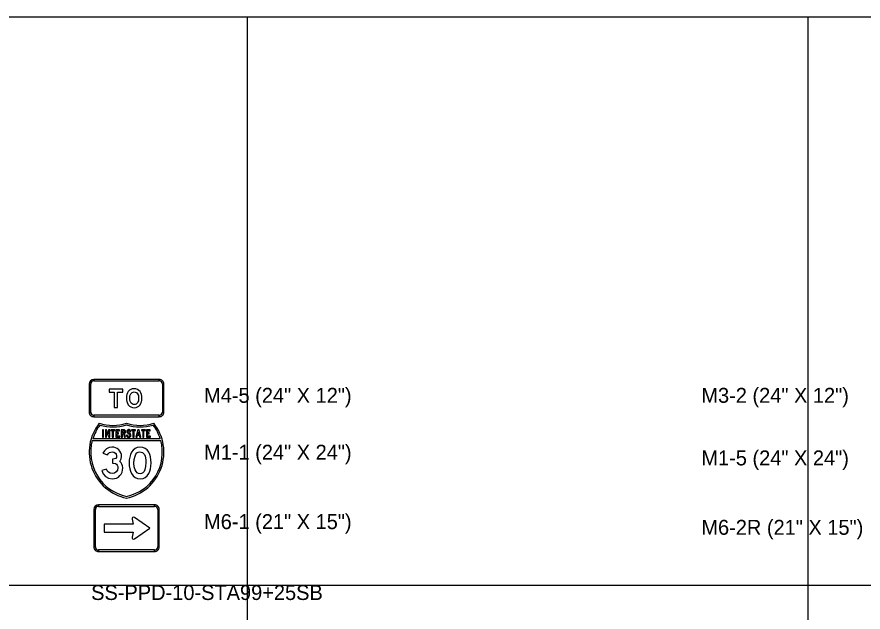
# Model space of a CAD drawing. Extents: x 1001568 to 1002149, y 1840825 to 1841423.
# Drawn here: x 1001914.49 to 1001937.13, y 1841294.75 to 1841310.67 of the extents above; entities that cross this region are included whole.
import ezdxf

# ---------------------------------------------------------------- set-up
doc = ezdxf.new("R2010")
doc.units = 0
for name, color, linetype in [('40', 7, 'Continuous'), ('R_No Plot', 7, 'Continuous'), ('SIGNS', 7, 'Continuous')]:
    doc.layers.add(name, color=color, linetype=linetype)

msp = doc.modelspace()

# ---------------------------------------------------------------- linework, layer by layer
at = {"layer": 'R_No Plot'}
for p, q in [((1001920.65, 1841310.667), (1001920.65, 1841248.127)), ((1001935.65, 1841310.667), (1001935.65, 1841248.127)), ((1001890.65, 1841295.469), (1001982.133, 1841295.469))]:
    msp.add_line(p, q, dxfattribs=at)
msp.add_lwpolyline([(1001886.411, 1841310.667), (1001964.232, 1841310.667), (1001964.232, 1841307.694), (1001968.454, 1841307.694), (1001968.454, 1841306.882), (1001982.133, 1841306.882), (1001982.133, 1841248.127), (1001886.411, 1841248.127)], close=True, dxfattribs=at)
at = {"layer": 'SIGNS'}
for p, q in [((1001916.42, 1841300.846), (1001916.42, 1841300.096)), ((1001916.42, 1841300.846), (1001916.462, 1841300.846)), ((1001918.295, 1841300.971), (1001916.545, 1841300.971)), ((1001916.545, 1841300.93), (1001916.545, 1841300.971)), ((1001918.295, 1841300.971), (1001918.295, 1841300.93)), ((1001918.379, 1841300.846), (1001918.42, 1841300.846)), ((1001918.42, 1841300.096), (1001918.42, 1841300.846)), ((1001916.462, 1841300.096), (1001916.42, 1841300.096)), ((1001916.545, 1841299.971), (1001916.545, 1841300.013)), ((1001916.545, 1841299.971), (1001918.295, 1841299.971)), ((1001918.295, 1841300.013), (1001918.295, 1841299.971)), ((1001918.42, 1841300.096), (1001918.379, 1841300.096)), ((1001916.808, 1841299.625), (1001916.78, 1841299.625)), ((1001916.78, 1841299.625), (1001916.78, 1841299.421)), ((1001916.808, 1841299.421), (1001916.808, 1841299.625)), ((1001916.883, 1841299.625), (1001916.855, 1841299.625)), ((1001916.855, 1841299.625), (1001916.855, 1841299.421)), ((1001916.939, 1841299.503), (1001916.883, 1841299.625)), ((1001916.883, 1841299.421), (1001916.883, 1841299.559)), ((1001916.883, 1841299.559), (1001916.947, 1841299.421)), ((1001916.97, 1841299.625), (1001916.939, 1841299.625)), ((1001916.939, 1841299.625), (1001916.939, 1841299.503)), ((1001916.97, 1841299.421), (1001916.97, 1841299.625)), ((1001917.105, 1841299.625), (1001917, 1841299.625)), ((1001917, 1841299.625), (1001917, 1841299.599)), ((1001917, 1841299.599), (1001917.038, 1841299.599)), ((1001917.038, 1841299.599), (1001917.038, 1841299.421)), ((1001917.067, 1841299.421), (1001917.067, 1841299.599)), ((1001917.067, 1841299.599), (1001917.105, 1841299.599)), ((1001917.105, 1841299.599), (1001917.105, 1841299.625)), ((1001917.233, 1841299.625), (1001917.136, 1841299.625)), ((1001917.136, 1841299.625), (1001917.136, 1841299.421)), ((1001917.166, 1841299.545), (1001917.166, 1841299.597)), ((1001917.166, 1841299.597), (1001917.233, 1841299.597)), ((1001917.208, 1841299.545), (1001917.166, 1841299.545)), ((1001917.166, 1841299.449), (1001917.166, 1841299.517)), ((1001917.166, 1841299.517), (1001917.208, 1841299.517)), ((1001917.241, 1841299.449), (1001917.166, 1841299.449)), ((1001917.208, 1841299.517), (1001917.208, 1841299.545)), ((1001917.233, 1841299.597), (1001917.233, 1841299.625)), ((1001917.241, 1841299.421), (1001917.241, 1841299.449)), ((1001917.447, 1841299.482), (1001917.419, 1841299.482)), ((1001917.419, 1841299.482), (1001917.419, 1841299.48)), ((1001917.419, 1841299.48), (1001917.42, 1841299.468)), ((1001917.42, 1841299.468), (1001917.423, 1841299.456)), ((1001917.423, 1841299.456), (1001917.428, 1841299.446)), ((1001917.432, 1841299.596), (1001917.428, 1841299.576)), ((1001917.428, 1841299.576), (1001917.429, 1841299.566)), ((1001917.428, 1841299.446), (1001917.435, 1841299.436)), ((1001917.429, 1841299.566), (1001917.432, 1841299.557)), ((1001917.444, 1841299.613), (1001917.432, 1841299.596)), ((1001917.432, 1841299.557), (1001917.437, 1841299.548)), ((1001917.435, 1841299.436), (1001917.444, 1841299.428)), ((1001917.437, 1841299.548), (1001917.444, 1841299.54)), ((1001917.452, 1841299.62), (1001917.444, 1841299.613)), ((1001917.444, 1841299.54), (1001917.477, 1841299.516)), ((1001917.449, 1841299.469), (1001917.447, 1841299.482)), ((1001917.455, 1841299.458), (1001917.449, 1841299.469)), ((1001917.461, 1841299.625), (1001917.452, 1841299.62)), ((1001917.464, 1841299.449), (1001917.455, 1841299.458)), ((1001917.457, 1841299.577), (1001917.459, 1841299.586)), ((1001917.458, 1841299.57), (1001917.457, 1841299.577)), ((1001917.461, 1841299.564), (1001917.458, 1841299.57)), ((1001917.459, 1841299.586), (1001917.464, 1841299.594)), ((1001917.47, 1841299.628), (1001917.461, 1841299.625)), ((1001917.477, 1841299.553), (1001917.461, 1841299.564)), ((1001917.464, 1841299.594), (1001917.472, 1841299.599)), ((1001917.477, 1841299.446), (1001917.464, 1841299.449)), ((1001917.481, 1841299.629), (1001917.47, 1841299.628)), ((1001917.472, 1841299.599), (1001917.482, 1841299.601)), ((1001917.501, 1841299.536), (1001917.477, 1841299.553)), ((1001917.477, 1841299.516), (1001917.49, 1841299.507)), ((1001917.489, 1841299.449), (1001917.477, 1841299.446)), ((1001917.492, 1841299.628), (1001917.481, 1841299.629)), ((1001917.482, 1841299.601), (1001917.492, 1841299.599)), ((1001917.498, 1841299.456), (1001917.489, 1841299.449)), ((1001917.49, 1841299.507), (1001917.497, 1841299.5)), ((1001917.502, 1841299.625), (1001917.492, 1841299.628)), ((1001917.492, 1841299.599), (1001917.499, 1841299.594)), ((1001917.497, 1841299.5), (1001917.504, 1841299.49)), ((1001917.504, 1841299.467), (1001917.498, 1841299.456)), ((1001917.499, 1841299.594), (1001917.503, 1841299.587)), ((1001917.516, 1841299.523), (1001917.501, 1841299.536)), ((1001917.511, 1841299.621), (1001917.502, 1841299.625)), ((1001917.503, 1841299.587), (1001917.506, 1841299.577)), ((1001917.504, 1841299.49), (1001917.506, 1841299.479)), ((1001917.506, 1841299.479), (1001917.504, 1841299.467)), ((1001917.506, 1841299.577), (1001917.534, 1841299.577)), ((1001917.51, 1841299.427), (1001917.519, 1841299.436)), ((1001917.519, 1841299.614), (1001917.511, 1841299.621)), ((1001917.524, 1841299.513), (1001917.516, 1841299.523)), ((1001917.53, 1841299.598), (1001917.519, 1841299.614)), ((1001917.519, 1841299.436), (1001917.526, 1841299.445)), ((1001917.53, 1841299.502), (1001917.524, 1841299.513)), ((1001917.526, 1841299.445), (1001917.531, 1841299.455)), ((1001917.534, 1841299.577), (1001917.53, 1841299.598)), ((1001917.533, 1841299.491), (1001917.53, 1841299.502)), ((1001917.531, 1841299.455), (1001917.533, 1841299.467)), ((1001917.534, 1841299.479), (1001917.533, 1841299.491)), ((1001917.533, 1841299.467), (1001917.534, 1841299.479)), ((1001917.66, 1841299.625), (1001917.555, 1841299.625)), ((1001917.555, 1841299.625), (1001917.555, 1841299.599)), ((1001917.555, 1841299.599), (1001917.592, 1841299.599)), ((1001917.592, 1841299.599), (1001917.592, 1841299.421)), ((1001917.622, 1841299.421), (1001917.622, 1841299.599)), ((1001917.622, 1841299.599), (1001917.66, 1841299.599)), ((1001917.66, 1841299.599), (1001917.66, 1841299.625)), ((1001917.924, 1841299.625), (1001917.819, 1841299.625)), ((1001917.819, 1841299.625), (1001917.819, 1841299.599)), ((1001917.819, 1841299.599), (1001917.856, 1841299.599)), ((1001917.856, 1841299.599), (1001917.856, 1841299.421)), ((1001917.886, 1841299.421), (1001917.886, 1841299.599)), ((1001917.886, 1841299.599), (1001917.924, 1841299.599)), ((1001917.924, 1841299.599), (1001917.924, 1841299.625)), ((1001918.052, 1841299.625), (1001917.955, 1841299.625)), ((1001917.955, 1841299.625), (1001917.955, 1841299.421)), ((1001917.984, 1841299.545), (1001917.984, 1841299.597)), ((1001917.984, 1841299.597), (1001918.052, 1841299.597)), ((1001918.027, 1841299.545), (1001917.984, 1841299.545)), ((1001917.984, 1841299.449), (1001917.984, 1841299.517)), ((1001917.984, 1841299.517), (1001918.027, 1841299.517)), ((1001918.06, 1841299.449), (1001917.984, 1841299.449)), ((1001918.027, 1841299.517), (1001918.027, 1841299.545)), ((1001918.052, 1841299.597), (1001918.052, 1841299.625)), ((1001918.06, 1841299.421), (1001918.06, 1841299.449)), ((1001918.324, 1841299.379), (1001916.516, 1841299.379)), ((1001916.78, 1841299.421), (1001916.808, 1841299.421)), ((1001916.855, 1841299.421), (1001916.883, 1841299.421)), ((1001916.947, 1841299.421), (1001916.97, 1841299.421)), ((1001917.038, 1841299.421), (1001917.067, 1841299.421)), ((1001917.136, 1841299.421), (1001917.241, 1841299.421)), ((1001917.444, 1841299.428), (1001917.454, 1841299.422)), ((1001917.454, 1841299.422), (1001917.465, 1841299.418)), ((1001917.465, 1841299.418), (1001917.477, 1841299.417)), ((1001917.477, 1841299.417), (1001917.489, 1841299.418)), ((1001917.489, 1841299.418), (1001917.5, 1841299.421)), ((1001917.5, 1841299.421), (1001917.51, 1841299.427)), ((1001917.592, 1841299.421), (1001917.622, 1841299.421)), ((1001917.856, 1841299.421), (1001917.886, 1841299.421)), ((1001917.955, 1841299.421), (1001918.06, 1841299.421)), ((1001916.545, 1841297.491), (1001916.587, 1841297.491)), ((1001916.67, 1841297.574), (1001916.67, 1841297.616)), ((1001918.17, 1841297.616), (1001918.17, 1841297.574)), ((1001918.254, 1841297.491), (1001918.295, 1841297.491)), ((1001917.567, 1841297.232), (1001917.597, 1841297.1)), ((1001918.045, 1841296.991), (1001917.63, 1841297.276)), ((1001917.597, 1841297.1), (1001916.826, 1841297.1)), ((1001916.826, 1841297.1), (1001916.826, 1841296.882)), ((1001917.63, 1841296.706), (1001918.045, 1841296.991)), ((1001916.826, 1841296.882), (1001917.597, 1841296.882)), ((1001917.597, 1841296.882), (1001917.567, 1841296.75)), ((1001916.587, 1841296.491), (1001916.545, 1841296.491)), ((1001916.67, 1841296.366), (1001916.67, 1841296.408)), ((1001918.17, 1841296.408), (1001918.17, 1841296.366)), ((1001918.295, 1841296.491), (1001918.254, 1841296.491))]:
    msp.add_line(p, q, dxfattribs=at)
for points in [[(1001916.42, 1841300.846), (1001916.42, 1841300.096), (1001916.462, 1841300.096), (1001916.462, 1841300.846), (1001916.42, 1841300.846), (1001916.42, 1841300.846)], [(1001918.295, 1841300.971), (1001916.545, 1841300.971), (1001916.545, 1841300.93), (1001918.295, 1841300.93), (1001918.295, 1841300.971), (1001918.295, 1841300.971)], [(1001918.42, 1841300.096), (1001918.42, 1841300.846), (1001918.379, 1841300.846), (1001918.379, 1841300.096), (1001918.42, 1841300.096), (1001918.42, 1841300.096)], [(1001917.093, 1841300.221), (1001917.179, 1841300.221), (1001917.179, 1841300.629), (1001917.322, 1841300.629), (1001917.322, 1841300.712), (1001916.951, 1841300.712), (1001916.951, 1841300.629), (1001917.093, 1841300.629)], [(1001916.545, 1841299.971), (1001918.295, 1841299.971), (1001918.295, 1841300.013), (1001916.545, 1841300.013), (1001916.545, 1841299.971), (1001916.545, 1841299.971)], [(1001916.758, 1841298.532), (1001916.795, 1841298.441), (1001916.859, 1841298.371), (1001916.942, 1841298.326), (1001917.04, 1841298.311), (1001917.1, 1841298.316), (1001917.155, 1841298.332), (1001917.202, 1841298.358), (1001917.244, 1841298.396), (1001917.276, 1841298.439), (1001917.299, 1841298.489), (1001917.313, 1841298.544), (1001917.318, 1841298.605), (1001917.313, 1841298.654), (1001917.298, 1841298.699), (1001917.274, 1841298.739), (1001917.24, 1841298.775), (1001917.274, 1841298.844), (1001917.286, 1841298.91), (1001917.281, 1841298.961), (1001917.267, 1841299.008), (1001917.244, 1841299.05), (1001917.211, 1841299.088), (1001917.171, 1841299.12), (1001917.128, 1841299.142), (1001917.08, 1841299.156), (1001917.029, 1841299.16), (1001916.953, 1841299.149), (1001916.884, 1841299.114), (1001916.827, 1841299.062), (1001916.79, 1841298.997), (1001916.912, 1841298.952), (1001916.934, 1841298.987), (1001916.962, 1841299.012), (1001916.996, 1841299.027), (1001917.036, 1841299.032), (1001917.082, 1841299.024), (1001917.121, 1841299.001), (1001917.147, 1841298.966), (1001917.156, 1841298.922), (1001917.15, 1841298.884), (1001917.132, 1841298.858), (1001917.101, 1841298.843), (1001917.059, 1841298.84), (1001917.043, 1841298.84), (1001917.043, 1841298.728), (1001917.05, 1841298.728), (1001917.121, 1841298.722), (1001917.15, 1841298.704), (1001917.171, 1841298.678), (1001917.183, 1841298.644), (1001917.187, 1841298.603), (1001917.177, 1841298.543), (1001917.145, 1841298.496), (1001917.098, 1841298.465), (1001917.04, 1841298.455), (1001916.985, 1841298.463), (1001916.939, 1841298.487), (1001916.904, 1841298.523), (1001916.885, 1841298.57)], [(1001916.545, 1841297.491), (1001916.545, 1841296.491), (1001916.587, 1841296.491), (1001916.587, 1841297.491), (1001916.545, 1841297.491), (1001916.545, 1841297.491)], [(1001918.17, 1841297.616), (1001916.67, 1841297.616), (1001916.67, 1841297.574), (1001918.17, 1841297.574), (1001918.17, 1841297.616), (1001918.17, 1841297.616)], [(1001918.295, 1841296.491), (1001918.295, 1841297.491), (1001918.254, 1841297.491), (1001918.254, 1841296.491), (1001918.295, 1841296.491), (1001918.295, 1841296.491)], [(1001916.67, 1841296.366), (1001918.17, 1841296.366), (1001918.17, 1841296.408), (1001916.67, 1841296.408), (1001916.67, 1841296.366), (1001916.67, 1841296.366)]]:
    msp.add_lwpolyline(points, close=True, dxfattribs=at)
for points in [[(1001917.832, 1841300.47), (1001917.829, 1841300.52), (1001917.819, 1841300.566), (1001917.803, 1841300.607), (1001917.781, 1841300.643), (1001917.75, 1841300.677), (1001917.713, 1841300.702), (1001917.67, 1841300.716), (1001917.622, 1841300.721), (1001917.574, 1841300.716), (1001917.532, 1841300.702), (1001917.496, 1841300.678), (1001917.465, 1841300.644), (1001917.444, 1841300.608), (1001917.429, 1841300.567), (1001917.42, 1841300.522), (1001917.417, 1841300.473), (1001917.42, 1841300.422), (1001917.429, 1841300.375), (1001917.444, 1841300.333), (1001917.466, 1841300.294), (1001917.497, 1841300.258), (1001917.534, 1841300.232), (1001917.577, 1841300.217), (1001917.626, 1841300.212), (1001917.674, 1841300.217), (1001917.717, 1841300.232), (1001917.753, 1841300.258), (1001917.784, 1841300.293), (1001917.805, 1841300.331), (1001917.82, 1841300.373), (1001917.829, 1841300.419), (1001917.832, 1841300.47)], [(1001917.743, 1841300.477), (1001917.741, 1841300.435), (1001917.736, 1841300.399), (1001917.726, 1841300.369), (1001917.714, 1841300.344), (1001917.697, 1841300.325), (1001917.677, 1841300.311), (1001917.653, 1841300.303), (1001917.626, 1841300.3), (1001917.596, 1841300.303), (1001917.57, 1841300.314), (1001917.548, 1841300.331), (1001917.531, 1841300.356), (1001917.512, 1841300.407), (1001917.506, 1841300.471), (1001917.512, 1841300.532), (1001917.531, 1841300.582), (1001917.549, 1841300.606), (1001917.571, 1841300.623), (1001917.596, 1841300.633), (1001917.626, 1841300.637), (1001917.654, 1841300.633), (1001917.679, 1841300.624), (1001917.7, 1841300.607), (1001917.717, 1841300.584), (1001917.737, 1841300.536), (1001917.743, 1841300.477)], [(1001916.69, 1841299.796), (1001916.69, 1841299.796)], [(1001916.705, 1841299.748), (1001916.705, 1841299.748)], [(1001917.42, 1841299.754), (1001917.42, 1841299.754)], [(1001918.135, 1841299.748), (1001918.135, 1841299.748)], [(1001918.151, 1841299.796), (1001918.151, 1841299.796)], [(1001917.31, 1841299.421), (1001917.31, 1841299.518), (1001917.337, 1841299.518), (1001917.364, 1841299.421), (1001917.393, 1841299.421), (1001917.363, 1841299.521), (1001917.376, 1841299.529), (1001917.385, 1841299.54), (1001917.391, 1841299.553), (1001917.393, 1841299.568), (1001917.392, 1841299.58), (1001917.389, 1841299.591), (1001917.385, 1841299.601), (1001917.379, 1841299.609), (1001917.371, 1841299.616), (1001917.362, 1841299.621), (1001917.351, 1841299.624), (1001917.339, 1841299.625), (1001917.277, 1841299.625), (1001917.277, 1841299.421), (1001917.31, 1841299.421)], [(1001917.31, 1841299.545), (1001917.31, 1841299.597), (1001917.339, 1841299.597), (1001917.35, 1841299.595), (1001917.358, 1841299.59), (1001917.364, 1841299.582), (1001917.366, 1841299.571), (1001917.364, 1841299.559), (1001917.359, 1841299.551), (1001917.351, 1841299.547), (1001917.34, 1841299.545), (1001917.31, 1841299.545)], [(1001917.703, 1841299.421), (1001917.717, 1841299.477), (1001917.761, 1841299.477), (1001917.775, 1841299.421), (1001917.805, 1841299.421), (1001917.754, 1841299.625), (1001917.725, 1841299.625), (1001917.673, 1841299.421), (1001917.703, 1841299.421)], [(1001917.724, 1841299.506), (1001917.738, 1841299.565), (1001917.754, 1841299.506), (1001917.724, 1841299.506)], [(1001916.504, 1841299.337), (1001917.047, 1841299.337), (1001917.574, 1841299.337), (1001918.336, 1841299.337)], [(1001917.78, 1841299.16), (1001917.709, 1841299.151), (1001917.647, 1841299.125), (1001917.595, 1841299.081), (1001917.552, 1841299.02), (1001917.525, 1841298.96), (1001917.506, 1841298.894), (1001917.495, 1841298.82), (1001917.491, 1841298.739), (1001917.495, 1841298.655), (1001917.506, 1841298.579), (1001917.525, 1841298.511), (1001917.552, 1841298.451), (1001917.595, 1841298.39), (1001917.649, 1841298.346), (1001917.713, 1841298.32), (1001917.788, 1841298.311), (1001917.861, 1841298.32), (1001917.923, 1841298.346), (1001917.976, 1841298.391), (1001918.019, 1841298.453), (1001918.044, 1841298.511), (1001918.062, 1841298.578), (1001918.072, 1841298.652), (1001918.076, 1841298.734), (1001918.072, 1841298.819), (1001918.061, 1841298.896), (1001918.043, 1841298.963), (1001918.018, 1841299.022), (1001917.975, 1841299.082), (1001917.921, 1841299.125), (1001917.856, 1841299.151), (1001917.78, 1841299.16)], [(1001917.94, 1841298.743), (1001917.932, 1841298.642), (1001917.911, 1841298.557), (1001917.888, 1841298.509), (1001917.859, 1841298.475), (1001917.824, 1841298.454), (1001917.783, 1841298.447), (1001917.74, 1841298.454), (1001917.704, 1841298.473), (1001917.674, 1841298.505), (1001917.65, 1841298.55), (1001917.627, 1841298.632), (1001917.619, 1841298.732), (1001917.626, 1841298.83), (1001917.648, 1841298.917), (1001917.671, 1841298.967), (1001917.699, 1841299.002), (1001917.733, 1841299.024), (1001917.773, 1841299.031), (1001917.812, 1841299.026), (1001917.846, 1841299.013), (1001917.874, 1841298.99), (1001917.898, 1841298.959), (1001917.916, 1841298.918), (1001917.929, 1841298.869), (1001917.937, 1841298.81), (1001917.94, 1841298.743)], [(1001917.42, 1841297.837), (1001917.42, 1841297.837)], [(1001917.42, 1841297.796), (1001917.42, 1841297.796)]]:
    msp.add_lwpolyline(points, dxfattribs=at)
for centre, radius, start, end in [((1001916.545, 1841300.846), 0.125, 90.0002, 179.9998), ((1001916.545, 1841300.846), 0.125, 90.0002, 179.9998), ((1001916.545, 1841300.846), 0.0833, 90.0002, 179.9998), ((1001918.295, 1841300.846), 0.125, 360, 90.0002), ((1001918.295, 1841300.846), 0.125, 360, 90.0002), ((1001918.295, 1841300.846), 0.0833, 360, 90.0002), ((1001916.545, 1841300.096), 0.125, 179.9998, 270.0001), ((1001916.545, 1841300.096), 0.125, 179.9998, 270.0001), ((1001916.545, 1841300.096), 0.0833, 179.9998, 270.0001), ((1001918.295, 1841300.096), 0.125, 270.0001, 0.0003), ((1001918.295, 1841300.096), 0.125, 270.0001, 0.0003), ((1001918.295, 1841300.096), 0.0833, 270.0001, 0.0003), ((1001917.67, 1841299.021), 1.25, 141.669, 258.463), ((1001917.67, 1841299.02), 1.208, 142.9959, 162.6952), ((1001917.055, 1841300.991), 1.25, 253.009, 286.9909), ((1001917.052, 1841300.992), 1.292, 254.4391, 286.5746), ((1001917.17, 1841299.021), 1.25, 281.5371, 38.3311), ((1001917.785, 1841300.991), 1.25, 253.0091, 286.9911), ((1001917.789, 1841300.992), 1.292, 253.4255, 285.561), ((1001917.17, 1841299.02), 1.208, 17.3047, 37.0041), ((1001917.67, 1841299.02), 1.208, 164.7534, 258.0704), ((1001917.17, 1841299.02), 1.208, 281.9296, 15.2467), ((1001917.17, 1841299.02), 1.208, 281.9296126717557, 281.9296393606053), ((1001917.67, 1841299.02), 1.208, 258.0704, 258.0705), ((1001916.67, 1841297.491), 0.125, 90.0002, 179.9998), ((1001916.67, 1841297.491), 0.0833, 90.0002, 179.9998), ((1001918.17, 1841297.491), 0.125, 0, 90.0002), ((1001918.17, 1841297.491), 0.0833, 0, 90.0002), ((1001917.608, 1841297.241), 0.0417, 57.7244, 192.9504), ((1001917.608, 1841296.741), 0.0417, 167.0499, 302.2759), ((1001916.67, 1841296.491), 0.125, 179.9998, 270.0001), ((1001916.67, 1841296.491), 0.0833, 179.9998, 270.0001), ((1001918.17, 1841296.491), 0.125, 270.0001, 0.0003), ((1001918.17, 1841296.491), 0.0833, 270.0001, 0.0003)]:
    msp.add_arc(centre, radius, start, end, dxfattribs=at)

# ---------------------------------------------------------------- texts
at = {"layer": '40'}
for s, p in [('M4-5 (24" X 12")', (1001919.495, 1841300.344)), ('M3-2 (24" X 12")', (1001932.801, 1841300.344)), ('M1-1 (24" X 24")', (1001919.495, 1841298.821)), ('M1-5 (24" X 24")', (1001932.801, 1841298.669)), ('M6-1 (21" X 15")', (1001919.495, 1841296.965)), ('M6-2R (21" X 15")', (1001932.801, 1841296.813)), ('SS-PPD-10-STA99+25SB', (1001916.473, 1841295.069))]:
    msp.add_text(s, height=0.4, rotation=0, dxfattribs=at).set_placement(p)

doc.saveas('drawing.dxf')
